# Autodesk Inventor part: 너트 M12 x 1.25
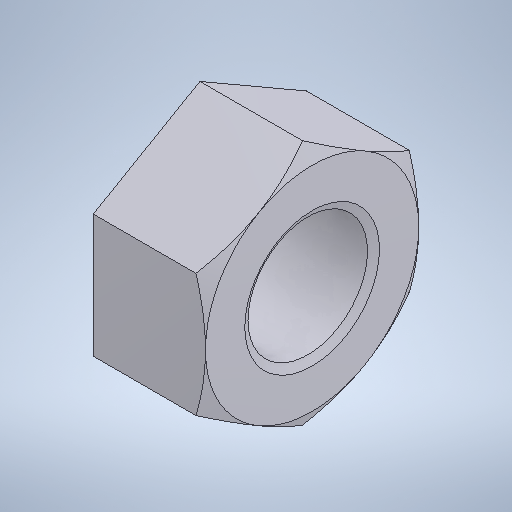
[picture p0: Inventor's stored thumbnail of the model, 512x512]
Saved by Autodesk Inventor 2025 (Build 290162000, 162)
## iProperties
Created: 2024-08
Part Number: 너트 M12 x 1.25
Material: 스테인리스강
Description: 6각 너트
Document SubType Name: Modeling
Designer: onair
Density: 8.08 g/cm^3
Appearance: 기본값
Author: jhkim
Sending System: Autodesk Inventor 2025
Preprocessor: ST-DEVELOPER v20
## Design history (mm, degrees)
feature "Solid1"
node "솔리드1"
